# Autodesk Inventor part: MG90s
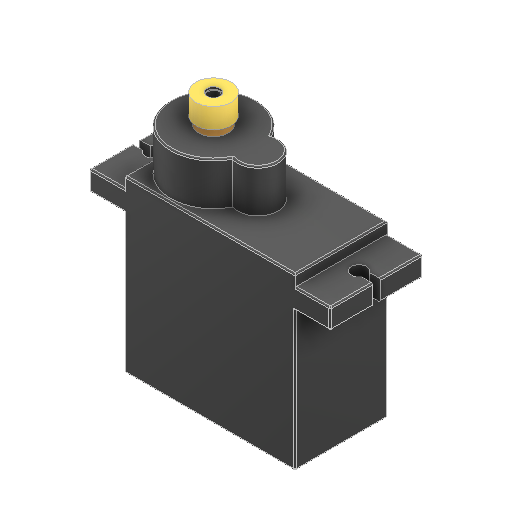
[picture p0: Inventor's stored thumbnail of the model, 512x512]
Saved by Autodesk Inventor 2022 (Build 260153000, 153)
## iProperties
Created: 2022-09
Part Number: MG90s
Material: Generico
Document SubType Name: Modeling
Designer: admin
Density: 1 g/cm^3
Appearance: Default
Author: admin
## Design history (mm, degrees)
feature "Solid1"
node "Solido1"
